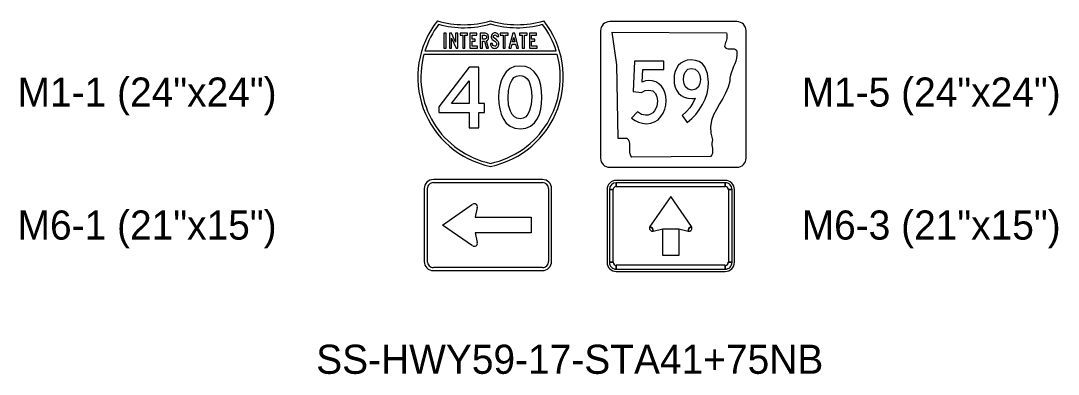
# Model space of a CAD drawing. Extents: x 620856.8 to 620948.6, y 415598.8 to 415658.2.
# Drawn here: x 620933.17 to 620947.43, y 415639.35 to 415644.2 of the extents above; entities that cross this region are included whole.
import ezdxf

# ---------------------------------------------------------------- set-up
doc = ezdxf.new("R2010")
doc.units = 0
doc.layers.add('SIGNS', color=7, linetype='Continuous')

msp = doc.modelspace()

# ---------------------------------------------------------------- linework, layer by layer
at = {"layer": 'SIGNS'}
for p, q in [((620943.018, 415644.189), (620941.268, 415644.189)), ((620939.018, 415644.031), (620938.989, 415644.031)), ((620938.989, 415644.031), (620938.989, 415643.826)), ((620939.018, 415643.826), (620939.018, 415644.031)), ((620939.093, 415644.031), (620939.064, 415644.031)), ((620939.064, 415644.031), (620939.064, 415643.826)), ((620939.149, 415643.909), (620939.093, 415644.031)), ((620939.093, 415643.826), (620939.093, 415643.964)), ((620939.093, 415643.964), (620939.157, 415643.826)), ((620939.18, 415644.031), (620939.149, 415644.031)), ((620939.149, 415644.031), (620939.149, 415643.909)), ((620939.18, 415643.826), (620939.18, 415644.031)), ((620939.315, 415644.031), (620939.21, 415644.031)), ((620939.21, 415644.031), (620939.21, 415644.005)), ((620939.21, 415644.005), (620939.248, 415644.005)), ((620939.248, 415644.005), (620939.248, 415643.826)), ((620939.277, 415643.826), (620939.277, 415644.005)), ((620939.277, 415644.005), (620939.315, 415644.005)), ((620939.315, 415644.005), (620939.315, 415644.031)), ((620939.443, 415644.031), (620939.346, 415644.031)), ((620939.346, 415644.031), (620939.346, 415643.826)), ((620939.376, 415643.95), (620939.376, 415644.002)), ((620939.376, 415644.002), (620939.443, 415644.002)), ((620939.418, 415643.95), (620939.376, 415643.95)), ((620939.418, 415643.922), (620939.418, 415643.95)), ((620939.443, 415644.002), (620939.443, 415644.031)), ((620939.642, 415644.002), (620939.638, 415643.982)), ((620939.638, 415643.982), (620939.639, 415643.971)), ((620939.639, 415643.971), (620939.642, 415643.962)), ((620939.654, 415644.019), (620939.642, 415644.002)), ((620939.642, 415643.962), (620939.647, 415643.953)), ((620939.647, 415643.953), (620939.654, 415643.945)), ((620939.662, 415644.026), (620939.654, 415644.019)), ((620939.654, 415643.945), (620939.687, 415643.922)), ((620939.671, 415644.031), (620939.662, 415644.026)), ((620939.667, 415643.983), (620939.669, 415643.992)), ((620939.668, 415643.976), (620939.667, 415643.983)), ((620939.671, 415643.97), (620939.668, 415643.976)), ((620939.669, 415643.992), (620939.674, 415643.999)), ((620939.68, 415644.034), (620939.671, 415644.031)), ((620939.687, 415643.958), (620939.671, 415643.97)), ((620939.674, 415643.999), (620939.682, 415644.005)), ((620939.691, 415644.035), (620939.68, 415644.034)), ((620939.682, 415644.005), (620939.691, 415644.006)), ((620939.711, 415643.942), (620939.687, 415643.958)), ((620939.702, 415644.034), (620939.691, 415644.035)), ((620939.691, 415644.006), (620939.702, 415644.005)), ((620939.712, 415644.031), (620939.702, 415644.034)), ((620939.702, 415644.005), (620939.709, 415644)), ((620939.709, 415644), (620939.713, 415643.993)), ((620939.726, 415643.928), (620939.711, 415643.942)), ((620939.721, 415644.026), (620939.712, 415644.031)), ((620939.713, 415643.993), (620939.716, 415643.983)), ((620939.716, 415643.983), (620939.744, 415643.983)), ((620939.729, 415644.02), (620939.721, 415644.026)), ((620939.734, 415643.918), (620939.726, 415643.928)), ((620939.74, 415644.003), (620939.729, 415644.02)), ((620939.744, 415643.983), (620939.74, 415644.003)), ((620939.87, 415644.031), (620939.764, 415644.031)), ((620939.764, 415644.031), (620939.764, 415644.005)), ((620939.764, 415644.005), (620939.802, 415644.005)), ((620939.802, 415644.005), (620939.802, 415643.826)), ((620939.831, 415643.826), (620939.831, 415644.005)), ((620939.831, 415644.005), (620939.87, 415644.005)), ((620939.87, 415644.005), (620939.87, 415644.031)), ((620940.134, 415644.031), (620940.029, 415644.031)), ((620940.029, 415644.031), (620940.029, 415644.005)), ((620940.029, 415644.005), (620940.066, 415644.005)), ((620940.066, 415644.005), (620940.066, 415643.826)), ((620940.096, 415643.826), (620940.096, 415644.005)), ((620940.096, 415644.005), (620940.134, 415644.005)), ((620940.134, 415644.005), (620940.134, 415644.031)), ((620940.262, 415644.031), (620940.164, 415644.031)), ((620940.164, 415644.031), (620940.164, 415643.826)), ((620940.194, 415643.95), (620940.194, 415644.002)), ((620940.194, 415644.002), (620940.262, 415644.002)), ((620940.237, 415643.95), (620940.194, 415643.95)), ((620940.237, 415643.922), (620940.237, 415643.95)), ((620940.262, 415644.002), (620940.262, 415644.031)), ((620941.143, 415644.064), (620941.143, 415642.314)), ((620943.143, 415642.314), (620943.143, 415644.064)), ((620940.534, 415643.785), (620938.726, 415643.785)), ((620938.989, 415643.826), (620939.018, 415643.826)), ((620939.064, 415643.826), (620939.093, 415643.826)), ((620939.157, 415643.826), (620939.18, 415643.826)), ((620939.248, 415643.826), (620939.277, 415643.826)), ((620939.346, 415643.826), (620939.451, 415643.826)), ((620939.376, 415643.854), (620939.376, 415643.922)), ((620939.376, 415643.922), (620939.418, 415643.922)), ((620939.451, 415643.854), (620939.376, 415643.854)), ((620939.451, 415643.826), (620939.451, 415643.854)), ((620939.657, 415643.888), (620939.629, 415643.888)), ((620939.629, 415643.888), (620939.629, 415643.886)), ((620939.629, 415643.886), (620939.63, 415643.873)), ((620939.63, 415643.873), (620939.633, 415643.862)), ((620939.633, 415643.862), (620939.638, 415643.851)), ((620939.638, 415643.851), (620939.645, 415643.842)), ((620939.645, 415643.842), (620939.654, 415643.833)), ((620939.654, 415643.833), (620939.664, 415643.827)), ((620939.659, 415643.874), (620939.657, 415643.888)), ((620939.665, 415643.863), (620939.659, 415643.874)), ((620939.664, 415643.827), (620939.675, 415643.823)), ((620939.674, 415643.855), (620939.665, 415643.863)), ((620939.687, 415643.852), (620939.674, 415643.855)), ((620939.675, 415643.823), (620939.687, 415643.822)), ((620939.687, 415643.922), (620939.699, 415643.912)), ((620939.699, 415643.854), (620939.687, 415643.852)), ((620939.687, 415643.822), (620939.699, 415643.823)), ((620939.699, 415643.912), (620939.707, 415643.905)), ((620939.708, 415643.862), (620939.699, 415643.854)), ((620939.699, 415643.823), (620939.71, 415643.827)), ((620939.707, 415643.905), (620939.714, 415643.895)), ((620939.714, 415643.872), (620939.708, 415643.862)), ((620939.71, 415643.827), (620939.72, 415643.833)), ((620939.714, 415643.895), (620939.716, 415643.884)), ((620939.716, 415643.884), (620939.714, 415643.872)), ((620939.72, 415643.833), (620939.729, 415643.841)), ((620939.729, 415643.841), (620939.736, 415643.85)), ((620939.74, 415643.908), (620939.734, 415643.918)), ((620939.736, 415643.85), (620939.74, 415643.861)), ((620939.743, 415643.896), (620939.74, 415643.908)), ((620939.74, 415643.861), (620939.743, 415643.872)), ((620939.744, 415643.885), (620939.743, 415643.896)), ((620939.743, 415643.872), (620939.744, 415643.885)), ((620939.802, 415643.826), (620939.831, 415643.826)), ((620940.066, 415643.826), (620940.096, 415643.826)), ((620940.164, 415643.826), (620940.27, 415643.826)), ((620940.194, 415643.854), (620940.194, 415643.922)), ((620940.194, 415643.922), (620940.237, 415643.922)), ((620940.27, 415643.854), (620940.194, 415643.854)), ((620940.27, 415643.826), (620940.27, 415643.854)), ((620941.143, 415642.314), (620941.143, 415642.314)), ((620941.268, 415642.189), (620943.018, 415642.189)), ((620940.344, 415642.021), (620938.844, 415642.021)), ((620938.844, 415642.021), (620938.844, 415642.021)), ((620938.844, 415641.98), (620940.344, 415641.98)), ((620942.857, 415642.009), (620941.357, 415642.009)), ((620941.357, 415641.926), (620941.357, 415641.978)), ((620942.857, 415641.978), (620942.857, 415641.926)), ((620938.719, 415641.896), (620938.719, 415640.896)), ((620938.761, 415640.896), (620938.761, 415641.896)), ((620940.427, 415641.896), (620940.427, 415640.896)), ((620940.469, 415640.896), (620940.469, 415641.896)), ((620941.232, 415641.884), (620941.232, 415640.884)), ((620941.263, 415641.884), (620941.316, 415641.884)), ((620942.899, 415641.884), (620942.951, 415641.884)), ((620942.982, 415640.884), (620942.982, 415641.884)), ((620938.969, 415641.396), (620939.384, 415641.682)), ((620939.447, 415641.637), (620939.417, 415641.506)), ((620939.417, 415641.506), (620940.188, 415641.506)), ((620940.188, 415641.506), (620940.188, 415641.287)), ((620939.384, 415641.111), (620938.969, 415641.396)), ((620941.857, 415641.353), (620941.822, 415641.375)), ((620942.392, 415641.375), (620942.357, 415641.353)), ((620940.188, 415641.287), (620939.417, 415641.287)), ((620939.417, 415641.287), (620939.447, 415641.156)), ((620941.867, 415641.312), (620941.857, 415641.353)), ((620942.357, 415641.353), (620942.348, 415641.312)), ((620940.344, 415640.813), (620938.844, 415640.813)), ((620941.316, 415640.884), (620941.263, 415640.884)), ((620941.357, 415640.79), (620941.357, 415640.843)), ((620942.857, 415640.843), (620942.857, 415640.79)), ((620942.951, 415640.884), (620942.899, 415640.884)), ((620938.844, 415640.771), (620940.344, 415640.771)), ((620940.344, 415640.771), (620940.344, 415640.771)), ((620941.357, 415640.759), (620942.857, 415640.759))]:
    msp.add_line(p, q, dxfattribs=at)
for points in [[(620938.9, 415644.201), (620938.9, 415644.201)], [(620938.915, 415644.153), (620938.915, 415644.153)], [(620939.63, 415644.16), (620939.63, 415644.16)], [(620940.345, 415644.153), (620940.345, 415644.153)], [(620940.361, 415644.201), (620940.361, 415644.201)], [(620941.268, 415644.189), (620941.268, 415644.189)], [(620943.018, 415644.189), (620943.018, 415644.189)], [(620939.519, 415643.826), (620939.519, 415643.923), (620939.547, 415643.923), (620939.573, 415643.826), (620939.603, 415643.826), (620939.573, 415643.927), (620939.586, 415643.934), (620939.595, 415643.945), (620939.601, 415643.958), (620939.603, 415643.973), (620939.602, 415643.986), (620939.599, 415643.997), (620939.595, 415644.006), (620939.589, 415644.015), (620939.581, 415644.022), (620939.572, 415644.027), (620939.561, 415644.03), (620939.549, 415644.031), (620939.487, 415644.031), (620939.487, 415643.826), (620939.519, 415643.826)], [(620939.519, 415643.95), (620939.519, 415644.002), (620939.549, 415644.002), (620939.56, 415644.001), (620939.568, 415643.995), (620939.574, 415643.987), (620939.576, 415643.976), (620939.574, 415643.965), (620939.569, 415643.957), (620939.561, 415643.952), (620939.55, 415643.95), (620939.519, 415643.95)], [(620939.913, 415643.826), (620939.927, 415643.882), (620939.971, 415643.882), (620939.985, 415643.826), (620940.015, 415643.826), (620939.964, 415644.031), (620939.935, 415644.031), (620939.883, 415643.826), (620939.913, 415643.826)], [(620939.934, 415643.912), (620939.948, 415643.971), (620939.964, 415643.912), (620939.934, 415643.912)], [(620941.143, 415644.064), (620941.143, 415644.064)], [(620938.714, 415643.743), (620939.257, 415643.743), (620939.784, 415643.743), (620940.546, 415643.743)], [(620942.264, 415642.9), (620942.333, 415642.805), (620942.395, 415642.858), (620942.451, 415642.916), (620942.5, 415642.98), (620942.544, 415643.05), (620942.58, 415643.126), (620942.606, 415643.203), (620942.622, 415643.281), (620942.627, 415643.36), (620942.614, 415643.479), (620942.577, 415643.57), (620942.542, 415643.611), (620942.499, 415643.64), (620942.448, 415643.657), (620942.39, 415643.663), (620942.335, 415643.658), (620942.287, 415643.644), (620942.246, 415643.62), (620942.211, 415643.586), (620942.185, 415643.547), (620942.166, 415643.503), (620942.155, 415643.454), (620942.152, 415643.399), (620942.155, 415643.342), (620942.167, 415643.291), (620942.186, 415643.247), (620942.213, 415643.209), (620942.249, 415643.176), (620942.292, 415643.153), (620942.341, 415643.139), (620942.398, 415643.134), (620942.422, 415643.136), (620942.445, 415643.137), (620942.443, 415643.137), (620942.409, 415643.068), (620942.368, 415643.006), (620942.32, 415642.95), (620942.264, 415642.9)], [(620939.335, 415642.733), (620939.467, 415642.733), (620939.467, 415642.942), (620939.547, 415642.942), (620939.547, 415643.063), (620939.467, 415643.063), (620939.467, 415643.564), (620939.335, 415643.564), (620938.919, 415643.021), (620938.919, 415642.942), (620939.335, 415642.942), (620939.335, 415642.733)], [(620940.034, 415643.58), (620939.961, 415643.571), (620939.899, 415643.544), (620939.846, 415643.5), (620939.802, 415643.438), (620939.775, 415643.377), (620939.756, 415643.309), (620939.744, 415643.234), (620939.74, 415643.152), (620939.744, 415643.067), (620939.756, 415642.99), (620939.775, 415642.92), (620939.802, 415642.859), (620939.846, 415642.797), (620939.901, 415642.752), (620939.966, 415642.726), (620940.042, 415642.717), (620940.116, 415642.726), (620940.18, 415642.753), (620940.233, 415642.798), (620940.276, 415642.861), (620940.302, 415642.92), (620940.32, 415642.988), (620940.331, 415643.064), (620940.335, 415643.147), (620940.331, 415643.234), (620940.32, 415643.311), (620940.301, 415643.38), (620940.275, 415643.439), (620940.231, 415643.501), (620940.177, 415643.545), (620940.111, 415643.571), (620940.034, 415643.58)], [(620942.515, 415643.396), (620942.508, 415643.34), (620942.487, 415643.295), (620942.45, 415643.261), (620942.398, 415643.25), (620942.348, 415643.261), (620942.311, 415643.293), (620942.291, 415643.337), (620942.284, 415643.392), (620942.289, 415643.45), (620942.307, 415643.497), (620942.343, 415643.535), (620942.394, 415643.548), (620942.445, 415643.536), (620942.485, 415643.5), (620942.507, 415643.453), (620942.515, 415643.396)], [(620939.335, 415643.063), (620939.095, 415643.063), (620939.335, 415643.377), (620939.335, 415643.063)], [(620940.196, 415643.156), (620940.189, 415643.053), (620940.167, 415642.967), (620940.144, 415642.918), (620940.114, 415642.884), (620940.078, 415642.863), (620940.036, 415642.856), (620939.993, 415642.862), (620939.957, 415642.882), (620939.926, 415642.914), (620939.902, 415642.96), (620939.878, 415643.044), (620939.87, 415643.144), (620939.878, 415643.244), (620939.9, 415643.333), (620939.923, 415643.383), (620939.952, 415643.42), (620939.986, 415643.441), (620940.027, 415643.449), (620940.066, 415643.444), (620940.101, 415643.43), (620940.13, 415643.407), (620940.154, 415643.375), (620940.172, 415643.334), (620940.185, 415643.284), (620940.193, 415643.224), (620940.196, 415643.156)], [(620939.63, 415642.243), (620939.63, 415642.243)], [(620939.63, 415642.201), (620939.63, 415642.201)], [(620941.268, 415642.189), (620941.268, 415642.189)], [(620943.018, 415642.189), (620943.018, 415642.189)], [(620940.344, 415642.021), (620940.344, 415642.021)], [(620940.469, 415641.896), (620940.469, 415641.896)], [(620938.719, 415640.896), (620938.719, 415640.896)], [(620938.844, 415640.771), (620938.844, 415640.771)]]:
    msp.add_lwpolyline(points, dxfattribs=at)
for points in [[(620942.873, 415644.035), (620942.878, 415644.016), (620942.88, 415643.996), (620942.879, 415643.977), (620942.877, 415643.958), (620942.873, 415643.939), (620942.868, 415643.92), (620942.862, 415643.901), (620942.856, 415643.883), (620942.851, 415643.864), (620942.846, 415643.846), (620942.86, 415643.83), (620942.878, 415643.821), (620942.897, 415643.817), (620942.919, 415643.816), (620942.94, 415643.817), (620942.961, 415643.817), (620942.98, 415643.815), (620942.996, 415643.809), (620943.01, 415643.797), (620943.018, 415643.777), (620943.018, 415643.731), (620943.013, 415643.688), (620943.002, 415643.648), (620942.987, 415643.61), (620942.972, 415643.571), (620942.956, 415643.534), (620942.941, 415643.495), (620942.929, 415643.455), (620942.92, 415643.414), (620942.918, 415643.37), (620942.896, 415643.288), (620942.862, 415643.209), (620942.822, 415643.134), (620942.778, 415643.059), (620942.735, 415642.984), (620942.697, 415642.908), (620942.669, 415642.83), (620942.654, 415642.747), (620942.658, 415642.66), (620942.683, 415642.566), (620942.676, 415642.543), (620942.673, 415642.519), (620942.674, 415642.495), (620942.677, 415642.471), (620942.68, 415642.447), (620942.683, 415642.424), (620942.683, 415642.401), (620942.68, 415642.379), (620942.672, 415642.358), (620942.656, 415642.338), (620941.573, 415642.328), (620941.558, 415642.348), (620941.55, 415642.372), (620941.546, 415642.398), (620941.546, 415642.426), (620941.546, 415642.456), (620941.547, 415642.485), (620941.545, 415642.514), (620941.539, 415642.541), (620941.528, 415642.565), (620941.509, 415642.586), (620941.383, 415642.586), (620941.365, 415643.598), (620941.302, 415644.045), (620942.873, 415644.035), (620942.873, 415644.035)], [(620941.568, 415642.863), (620941.616, 415642.83), (620941.666, 415642.807), (620941.718, 415642.793), (620941.773, 415642.788), (620941.832, 415642.794), (620941.885, 415642.812), (620941.932, 415642.843), (620941.973, 415642.886), (620942.004, 415642.933), (620942.026, 415642.986), (620942.039, 415643.044), (620942.043, 415643.107), (620942.04, 415643.164), (620942.028, 415643.216), (620942.009, 415643.262), (620941.981, 415643.303), (620941.945, 415643.337), (620941.903, 415643.362), (620941.854, 415643.377), (620941.799, 415643.382), (620941.758, 415643.376), (620941.714, 415643.356), (620941.723, 415643.531), (620942.01, 415643.531), (620942.01, 415643.647), (620941.61, 415643.647), (620941.589, 415643.231), (620941.706, 415643.216), (620941.755, 415643.242), (620941.807, 415643.25), (620941.86, 415643.239), (620941.897, 415643.204), (620941.917, 415643.158), (620941.924, 415643.101), (620941.914, 415643.026), (620941.884, 415642.965), (620941.859, 415642.938), (620941.831, 415642.919), (620941.797, 415642.907), (620941.76, 415642.904), (620941.703, 415642.915), (620941.649, 415642.951)], [(620942.857, 415641.978), (620941.357, 415641.978), (620941.357, 415641.926), (620942.857, 415641.926), (620942.857, 415641.978), (620942.857, 415641.978)], [(620941.263, 415641.884), (620941.263, 415640.884), (620941.316, 415640.884), (620941.316, 415641.884), (620941.263, 415641.884), (620941.263, 415641.884)], [(620942.107, 415641.79), (620941.822, 415641.375), (620941.857, 415641.353), (620941.867, 415641.312), (620941.998, 415641.343), (620942.217, 415641.343), (620942.348, 415641.312), (620942.357, 415641.353), (620942.392, 415641.375), (620942.107, 415641.79), (620942.107, 415641.79)], [(620942.951, 415640.884), (620942.951, 415641.884), (620942.899, 415641.884), (620942.899, 415640.884), (620942.951, 415640.884), (620942.951, 415640.884)], [(620942.217, 415640.978), (620941.998, 415640.978), (620941.998, 415641.343), (620942.217, 415641.343), (620942.217, 415640.978), (620942.217, 415640.978)], [(620941.357, 415640.79), (620942.857, 415640.79), (620942.857, 415640.843), (620941.357, 415640.843), (620941.357, 415640.79), (620941.357, 415640.79)]]:
    msp.add_lwpolyline(points, close=True, dxfattribs=at)
for centre, radius, start, end in [((620939.88, 415643.426), 1.25, 141.669, 258.463), ((620939.88, 415643.425), 1.208, 142.9959, 162.6952), ((620939.265, 415645.397), 1.25, 253.009, 286.9909), ((620939.262, 415645.398), 1.292, 254.4391, 286.5746), ((620939.38, 415643.426), 1.25, 281.5371, 38.3311), ((620939.995, 415645.397), 1.25, 253.0091, 286.9911), ((620939.999, 415645.398), 1.292, 253.4255, 285.561), ((620939.38, 415643.425), 1.208, 17.3047, 37.0041), ((620941.268, 415644.064), 0.125, 90.0002, 179.9998), ((620943.018, 415644.064), 0.125, 360, 90), ((620939.88, 415643.425), 1.208, 164.7534, 258.0704), ((620939.38, 415643.425), 1.208, 281.9296, 15.2467), ((620939.38, 415643.425), 1.208, 281.92961185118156, 281.92963854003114), ((620939.88, 415643.425), 1.208, 258.0704, 258.0705), ((620941.268, 415642.314), 0.125, 180, 270), ((620943.018, 415642.314), 0.125, 270.0001, 0.0003), ((620938.844, 415641.896), 0.125, 90, 180), ((620938.844, 415641.896), 0.0833, 89.9998, 180), ((620940.344, 415641.896), 0.125, 0.0002, 89.9998), ((620940.344, 415641.896), 0.0833, 0.0002, 89.9998), ((620941.357, 415641.884), 0.125, 90.0002, 179.9998), ((620941.357, 415641.884), 0.0937, 90.0002, 179.9998), ((620942.857, 415641.884), 0.125, 360, 90.0002), ((620942.857, 415641.884), 0.0937, 360, 90.0002), ((620941.357, 415641.884), 0.0417, 90.0002, 179.9998), ((620942.857, 415641.884), 0.0417, 360, 90.0002), ((620939.407, 415641.646), 0.0417, 347.0496, 122.2756), ((620941.857, 415641.353), 0.0417, 147.7246, 282.9506), ((620942.357, 415641.353), 0.0417, 257.0495, 32.2756), ((620939.407, 415641.146), 0.0417, 237.7241, 12.9501), ((620938.844, 415640.896), 0.125, 180, 269.9999), ((620938.844, 415640.896), 0.0833, 179.9997, 269.9999), ((620940.344, 415640.896), 0.125, 270, 0.0002), ((620940.344, 415640.896), 0.0833, 269.9999, 0.0002), ((620941.357, 415640.884), 0.125, 179.9998, 270.0001), ((620941.357, 415640.884), 0.0937, 179.9998, 270.0001), ((620941.357, 415640.884), 0.0417, 179.9998, 270.0001), ((620942.857, 415640.884), 0.0937, 270.0001, 0.0003), ((620942.857, 415640.884), 0.0417, 270.0001, 0.0003), ((620942.857, 415640.884), 0.125, 270.0001, 0.0003)]:
    msp.add_arc(centre, radius, start, end, dxfattribs=at)

# ---------------------------------------------------------------- texts
for s, p in [('M1-1 (24"x24")', (620933.128, 415643.022)), ('M1-5 (24"x24")', (620943.907, 415643.022)), ('M6-1 (21"x15")', (620933.128, 415641.196)), ('M6-3 (21"x15")', (620943.907, 415641.196)), ('SS-HWY59-17-STA41+75NB', (620937.233, 415639.353))]:
    msp.add_text(s, height=0.4, rotation=0, dxfattribs=at).set_placement(p)

doc.saveas('drawing.dxf')
